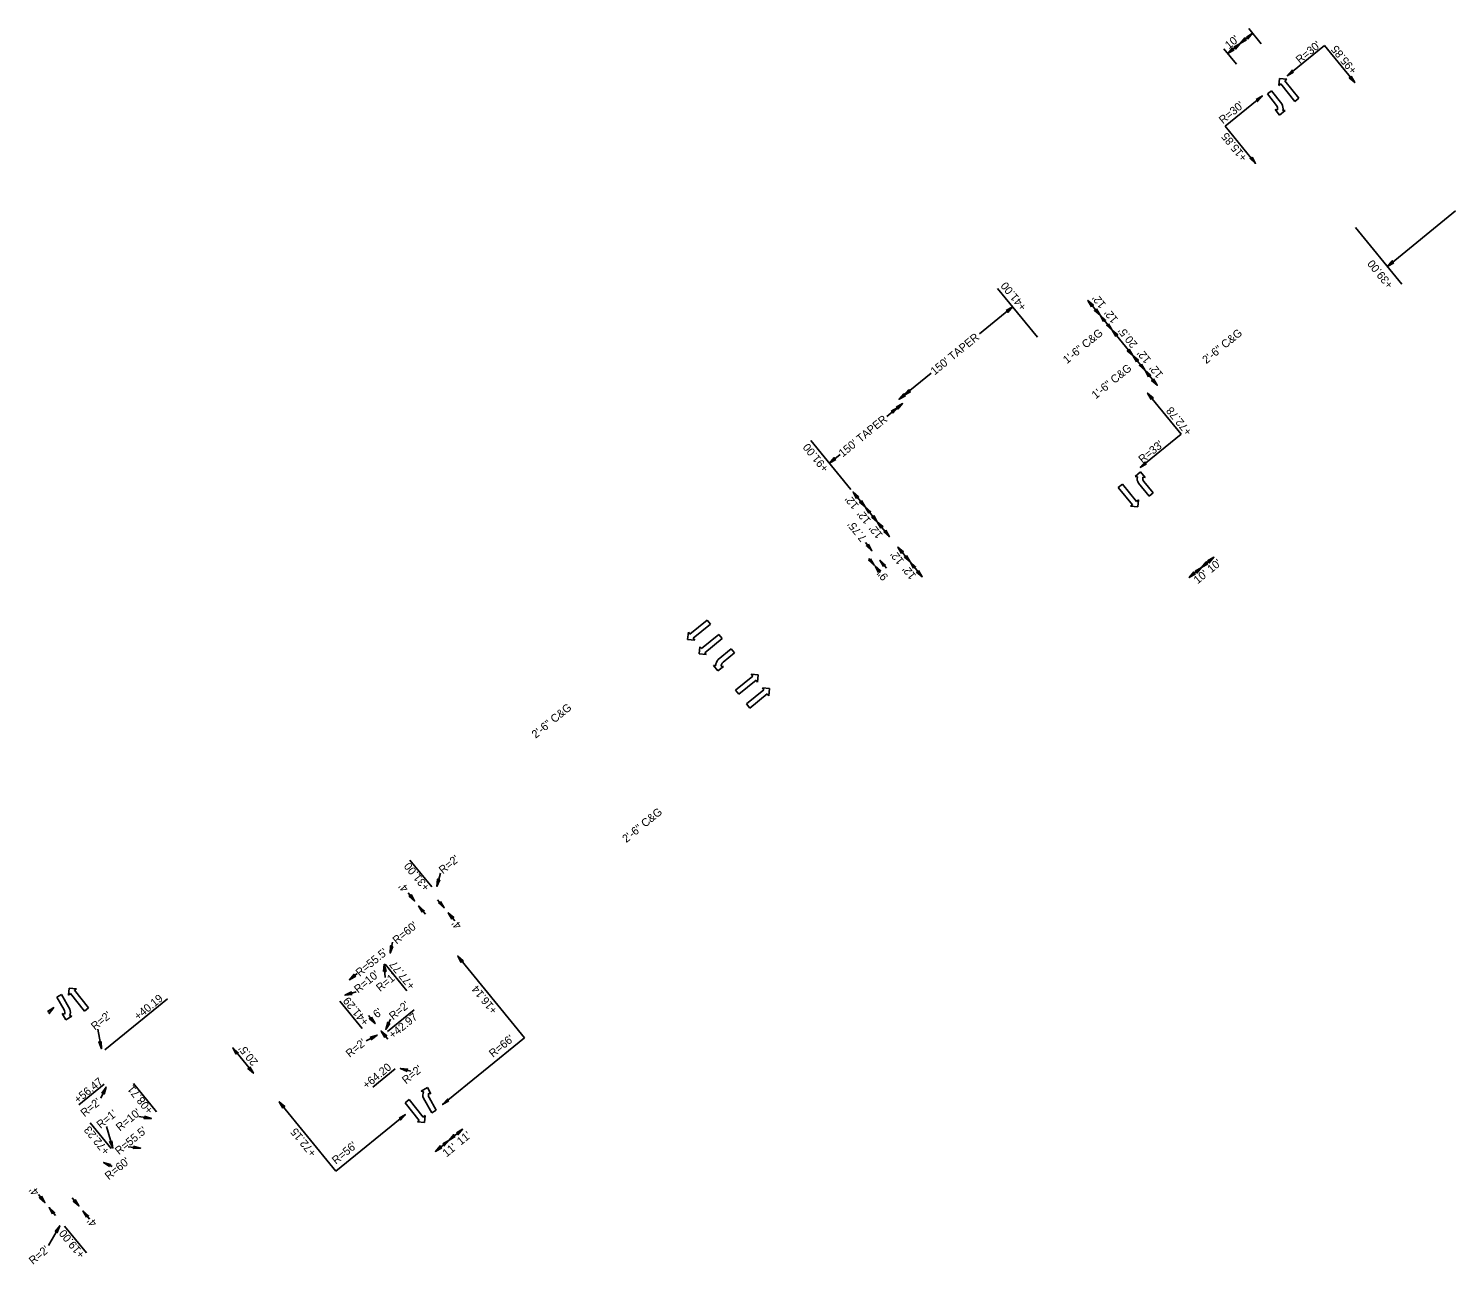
# Model space of a CAD drawing. Extents: x 2320991 to 2332664, y 598057 to 612602.
# Drawn here: x 2322910 to 2323802, y 599000 to 599773 of the extents above; entities that cross this region are included whole.
import ezdxf

# ---------------------------------------------------------------- set-up
doc = ezdxf.new("R2010")
doc.units = 0
for name, color, linetype in [('Prop Dimension', 7, 'Continuous'), ('Prop Dimension Text', 7, 'Continuous'), ('Prop Lane Arrow CELL', 7, 'Continuous'), ('Prop Terminator CELL', 7, 'Continuous')]:
    doc.layers.add(name, color=color, linetype=linetype)

msp = doc.modelspace()

# ---------------------------------------------------------------- linework, layer by layer
at = {"layer": 'Prop Dimension'}
for p, q in [((2323660.06, 599757.48), (2323675.51, 599770.18)), ((2323697.16, 599743.67), (2323720.4, 599762.64)), ((2323739.37, 599739.4), (2323720.4, 599762.64)), ((2323681.66, 599731.02), (2323658.42, 599712.05)), ((2323677.4, 599688.81), (2323658.42, 599712.05)), ((2323759.79, 599624.48), (2323802.28, 599659.17)), ((2323739.91, 599648.83), (2323768.82, 599613.43)), ((2323516.03, 599610.67), (2323540.97, 599580.12)), ((2323504.78, 599582.33), (2323525.41, 599599.18)), ((2323572.54, 599603.2), (2323580.13, 599593.91)), ((2323580.13, 599593.91), (2323587.72, 599584.61)), ((2323587.72, 599584.61), (2323600.68, 599568.73)), ((2323600.68, 599568.73), (2323608.27, 599559.44)), ((2323454.59, 599541.36), (2323474.68, 599557.76)), ((2323608.27, 599559.44), (2323615.86, 599550.14)), ((2323609.89, 599545.27), (2323630.81, 599519.65)), ((2323446.89, 599530.69), (2323456.74, 599538.73)), ((2323605.25, 599498.78), (2323630.81, 599519.65)), ((2323399.49, 599515.53), (2323424.48, 599484.91)), ((2323411.02, 599501.41), (2323417.66, 599506.83)), ((2323433.34, 599474.07), (2323425.75, 599483.36)), ((2323440.93, 599464.77), (2323433.34, 599474.07)), ((2323448.52, 599455.47), (2323440.93, 599464.77)), ((2323433.5, 599451.76), (2323437.62, 599446.73)), ((2323461.41, 599439.68), (2323453.82, 599448.98)), ((2323435.71, 599441.78), (2323439.03, 599437.72)), ((2323439.5, 599437.14), (2323442.81, 599433.09)), ((2323442.52, 599440.72), (2323446.63, 599435.69)), ((2323469, 599430.39), (2323461.41, 599439.68)), ((2323635.86, 599429.91), (2323651.31, 599442.61)), ((2323162.54, 599236.53), (2323148.86, 599253.29)), ((2323165.72, 599236.83), (2323167.87, 599245.04)), ((2323147.65, 599232.76), (2323151.76, 599227.73)), ((2323154.29, 599224.63), (2323158.48, 599219.49)), ((2323166.14, 599228.5), (2323170.25, 599223.46)), ((2323172.78, 599220.36), (2323176.98, 599215.23)), ((2323136.52, 599195.11), (2323138.03, 599202.04)), ((2323132.77, 599188.15), (2323133.42, 599179.98)), ((2323133.32, 599188.15), (2323146.88, 599171.53)), ((2323178.69, 599193.24), (2323220.39, 599142.17)), ((2323115.8, 599182.37), (2323110.97, 599178.43)), ((2323108.17, 599168.73), (2323115.28, 599170.97)), ((2322958.21, 599134.66), (2322997.35, 599166.61)), ((2323105.06, 599165.08), (2323118.96, 599148.05)), ((2323134.9, 599146.21), (2323151.4, 599159.68)), ((2323127.04, 599151.07), (2323122.92, 599156.11)), ((2323133.72, 599147.47), (2323136.78, 599153.88)), ((2322956.01, 599135.29), (2322953.71, 599147.52)), ((2323128.4, 599143.88), (2323121.56, 599140.29)), ((2323130.83, 599146.42), (2323134.94, 599141.38)), ((2323169.26, 599100.43), (2323220.39, 599142.17)), ((2323038.06, 599135.88), (2323051.03, 599120)), ((2323125.61, 599111.23), (2323139.66, 599122.7)), ((2323142.9, 599123.03), (2323149.34, 599121.36)), ((2322957.72, 599113.16), (2322941.96, 599100.3)), ((2322958.89, 599111.4), (2322955.66, 599104.42)), ((2322990.35, 599095.95), (2322976, 599113.53)), ((2323067.16, 599102.18), (2323102.61, 599058.75)), ((2322962.09, 599072.88), (2322948.88, 599089.06)), ((2322987.28, 599091.82), (2322979.47, 599092.96)), ((2323145.99, 599094.17), (2323102.61, 599058.75)), ((2322963.17, 599073.19), (2322959.13, 599086.63)), ((2323164.73, 599071.16), (2323181.79, 599085.05)), ((2322980.47, 599073.27), (2322972.63, 599074.06)), ((2322957.32, 599064.22), (2322962.68, 599061.73)), ((2322916.63, 599044.16), (2322920.74, 599039.13)), ((2322923.27, 599036.03), (2322927.38, 599031)), ((2322937.83, 599042.11), (2322941.94, 599037.07)), ((2322944.47, 599033.97), (2322948.66, 599028.84)), ((2322944.47, 599033.97), (2322948.58, 599028.94)), ((2322929.95, 599024.7), (2322922.92, 599012.38)), ((2322932.87, 599024.5), (2322946.63, 599007.65))]:
    msp.add_line(p, q, dxfattribs=at)
at = {"layer": 'Prop Dimension Text'}
for p, q in [((2323680.87, 599763.61), (2323673.07, 599773.17)), ((2323665.38, 599750.96), (2323657.58, 599760.52))]:
    msp.add_line(p, q, dxfattribs=at)
at = {"layer": 'Prop Lane Arrow CELL'}
for p, q in [((2323691.9, 599737.55), (2323692.32, 599741.95)), ((2323692.32, 599741.95), (2323696.79, 599741.52)), ((2323696.79, 599741.52), (2323695.63, 599740.57)), ((2323695.63, 599740.57), (2323704.45, 599729.7)), ((2323684.73, 599732.28), (2323687.33, 599734.31)), ((2323690.38, 599725.08), (2323684.73, 599732.28)), ((2323687.33, 599734.31), (2323693.84, 599726.01)), ((2323693.07, 599738.49), (2323691.9, 599737.55)), ((2323701.89, 599727.62), (2323693.07, 599738.49)), ((2323692.36, 599719.07), (2323689.54, 599722.58)), ((2323689.54, 599722.58), (2323691.01, 599722.4)), ((2323695.79, 599721.82), (2323692.36, 599719.07)), ((2323694.31, 599722), (2323695.79, 599721.82)), ((2323704.45, 599729.7), (2323701.89, 599727.62)), ((2323602.11, 599493.12), (2323605.5, 599495.93)), ((2323603.59, 599492.96), (2323602.11, 599493.12)), ((2323605.5, 599495.93), (2323608.37, 599492.46)), ((2323608.37, 599492.46), (2323606.89, 599492.61)), ((2323607.57, 599489.95), (2323613.33, 599482.84)), ((2323591.56, 599486.32), (2323594.13, 599488.4)), ((2323600.39, 599475.45), (2323591.56, 599486.32)), ((2323594.13, 599488.4), (2323602.95, 599477.53)), ((2323610.76, 599480.76), (2323604.13, 599488.96)), ((2323613.33, 599482.84), (2323610.76, 599480.76)), ((2323599.22, 599474.5), (2323600.39, 599475.45)), ((2323603.69, 599474.07), (2323599.22, 599474.5)), ((2323602.95, 599477.53), (2323604.11, 599478.47)), ((2323604.11, 599478.47), (2323603.69, 599474.07)), ((2323323.79, 599394.55), (2323334.66, 599403.37)), ((2323336.74, 599400.81), (2323325.87, 599391.99)), ((2323334.66, 599403.37), (2323336.74, 599400.81)), ((2323322.41, 599391.24), (2323322.84, 599395.71)), ((2323326.81, 599390.82), (2323322.41, 599391.24)), ((2323322.84, 599395.71), (2323323.79, 599394.55)), ((2323325.87, 599391.99), (2323326.81, 599390.82)), ((2323330.99, 599385.5), (2323341.86, 599394.32)), ((2323343.94, 599391.76), (2323333.07, 599382.94)), ((2323341.86, 599394.32), (2323343.94, 599391.76)), ((2323329.62, 599382.19), (2323330.05, 599386.66)), ((2323334.02, 599381.77), (2323329.62, 599382.19)), ((2323330.05, 599386.66), (2323330.99, 599385.5)), ((2323333.07, 599382.94), (2323334.02, 599381.77)), ((2323349.58, 599385.34), (2323341.41, 599378.66)), ((2323344.58, 599376.99), (2323351.67, 599382.78)), ((2323351.67, 599382.78), (2323349.58, 599385.34)), ((2323340.06, 599374.86), (2323338.58, 599375)), ((2323338.58, 599375), (2323341.33, 599371.56)), ((2323341.33, 599371.56), (2323344.85, 599374.37)), ((2323344.85, 599374.37), (2323343.37, 599374.52)), ((2323352.22, 599359.48), (2323363.09, 599368.3)), ((2323365.17, 599365.74), (2323354.3, 599356.92)), ((2323363.09, 599368.3), (2323362.15, 599369.47)), ((2323362.15, 599369.47), (2323366.55, 599369.04)), ((2323366.12, 599364.58), (2323365.17, 599365.74)), ((2323366.55, 599369.04), (2323366.12, 599364.58)), ((2323354.3, 599356.92), (2323352.22, 599359.48)), ((2323359.22, 599350.91), (2323370.09, 599359.73)), ((2323372.17, 599357.17), (2323361.3, 599348.35)), ((2323370.09, 599359.73), (2323369.14, 599360.9)), ((2323369.14, 599360.9), (2323373.54, 599360.47)), ((2323373.11, 599356), (2323372.17, 599357.17)), ((2323373.54, 599360.47), (2323373.11, 599356)), ((2323361.3, 599348.35), (2323359.22, 599350.91)), ((2322928.2, 599167.6), (2322931.07, 599169.23)), ((2322931.07, 599169.23), (2322936.27, 599160.05)), ((2322935.5, 599168.85), (2322935.92, 599173.25)), ((2322936.66, 599169.8), (2322935.5, 599168.85)), ((2322935.92, 599173.25), (2322940.39, 599172.82)), ((2322945.48, 599158.93), (2322936.66, 599169.8)), ((2322940.39, 599172.82), (2322939.22, 599171.88)), ((2322939.22, 599171.88), (2322948.04, 599161.01)), ((2322932.71, 599159.64), (2322928.2, 599167.6)), ((2322948.04, 599161.01), (2322945.48, 599158.93)), ((2322933.78, 599153.41), (2322931.52, 599157.3)), ((2322931.52, 599157.3), (2322932.95, 599156.9)), ((2322937.58, 599155.62), (2322933.78, 599153.41)), ((2322936.15, 599156.02), (2322937.58, 599155.62)), ((2323155.93, 599108.82), (2323159.73, 599111.04)), ((2323157.36, 599108.43), (2323155.93, 599108.82)), ((2323159.73, 599111.04), (2323162, 599107.15)), ((2323162, 599107.15), (2323160.57, 599107.54)), ((2323145.8, 599101.43), (2323148.36, 599103.51)), ((2323154.62, 599090.56), (2323145.8, 599101.43)), ((2323148.36, 599103.51), (2323157.18, 599092.64)), ((2323162.45, 599095.22), (2323157.24, 599104.39)), ((2323160.8, 599104.8), (2323165.32, 599096.84)), ((2323165.32, 599096.84), (2323162.45, 599095.22)), ((2323153.46, 599089.62), (2323154.62, 599090.56)), ((2323157.93, 599089.19), (2323153.46, 599089.62)), ((2323157.18, 599092.64), (2323158.35, 599093.59)), ((2323158.35, 599093.59), (2323157.93, 599089.19))]:
    msp.add_line(p, q, dxfattribs=at)
for centre, radius, start, end in [((2323687.82, 599723.06), 3.27, 348.43667, 38.09484), ((2323689.28, 599723.44), 5.25, 344.10707, 29.41877), ((2323608.65, 599491.6), 5.25, 165.00564, 210.31734), ((2323610.1, 599492.01), 3.27, 169.33523, 218.99341), ((2323345.29, 599375.16), 5.25, 137.90406, 183.21576), ((2323346.63, 599374.46), 3.27, 129.22799, 178.88617), ((2322929.88, 599158.02), 3.27, 339.9172, 29.57538), ((2322931.38, 599158.19), 5.25, 335.58761, 20.89931), ((2323162.13, 599106.26), 5.25, 155.58761, 200.89931), ((2323163.63, 599106.42), 3.27, 159.9172, 209.57538)]:
    msp.add_arc(centre, radius, start, end, dxfattribs=at)
at = {"layer": 'Prop Terminator CELL'}
for points in [[(2323671.72, 599766.16), (2323667.79, 599763.83), (2323670.71, 599767.37), (2323670.79, 599766.39)], [(2323671.58, 599767.85), (2323675.51, 599770.18), (2323672.58, 599766.64), (2323672.5, 599767.62)], [(2323663.99, 599759.8), (2323660.06, 599757.48), (2323662.99, 599761.02), (2323663.07, 599760.04)], [(2323663.86, 599761.5), (2323667.79, 599763.83), (2323664.86, 599760.28), (2323664.78, 599761.27)], [(2323701.13, 599745.91), (2323697.16, 599743.67), (2323700.16, 599747.15), (2323700.22, 599746.16)], [(2323737.12, 599743.38), (2323739.37, 599739.4), (2323735.89, 599742.4), (2323736.87, 599742.46)], [(2323677.69, 599728.77), (2323681.66, 599731.02), (2323678.66, 599727.54), (2323678.6, 599728.52)], [(2323675.15, 599692.78), (2323677.4, 599688.81), (2323673.92, 599691.81), (2323674.9, 599691.87)], [(2323763.77, 599626.73), (2323759.79, 599624.48), (2323762.79, 599627.97), (2323762.85, 599626.98)], [(2323521.44, 599596.93), (2323525.41, 599599.18), (2323522.42, 599595.69), (2323522.35, 599596.68)], [(2323574.79, 599599.23), (2323572.54, 599603.2), (2323576.02, 599600.2), (2323575.04, 599600.14)], [(2323577.88, 599597.88), (2323580.13, 599593.91), (2323576.65, 599596.91), (2323577.63, 599596.97)], [(2323582.38, 599589.93), (2323580.13, 599593.91), (2323583.61, 599590.91), (2323582.63, 599590.85)], [(2323585.47, 599588.59), (2323587.72, 599584.61), (2323584.24, 599587.61), (2323585.22, 599587.67)], [(2323589.96, 599580.64), (2323587.72, 599584.61), (2323591.2, 599581.61), (2323590.22, 599581.55)], [(2323598.44, 599572.71), (2323600.68, 599568.73), (2323597.2, 599571.73), (2323598.19, 599571.79)], [(2323602.93, 599564.76), (2323600.68, 599568.73), (2323604.16, 599565.73), (2323603.18, 599565.67)], [(2323606.03, 599563.41), (2323608.27, 599559.44), (2323604.79, 599562.44), (2323605.77, 599562.5)], [(2323610.52, 599555.46), (2323608.27, 599559.44), (2323611.75, 599556.44), (2323610.77, 599556.38)], [(2323613.62, 599554.12), (2323615.86, 599550.14), (2323612.38, 599553.14), (2323613.36, 599553.2)], [(2323458.57, 599543.6), (2323454.59, 599541.36), (2323457.59, 599544.84), (2323457.65, 599543.86)], [(2323461.63, 599546.1), (2323457.65, 599543.86), (2323460.65, 599547.34), (2323460.71, 599546.35)], [(2323612.14, 599541.29), (2323609.89, 599545.27), (2323613.37, 599542.27), (2323612.39, 599542.21)], [(2323449.7, 599533.99), (2323453.68, 599536.23), (2323450.68, 599532.75), (2323450.62, 599533.74)], [(2323452.76, 599536.49), (2323456.74, 599538.73), (2323453.74, 599535.25), (2323453.68, 599536.23)], [(2323415, 599503.65), (2323411.02, 599501.41), (2323414.02, 599504.89), (2323414.08, 599503.9)], [(2323609.22, 599501.02), (2323605.25, 599498.78), (2323608.25, 599502.26), (2323608.31, 599501.28)], [(2323428, 599479.39), (2323425.75, 599483.36), (2323429.23, 599480.37), (2323428.25, 599480.31)], [(2323431.09, 599478.05), (2323433.34, 599474.07), (2323429.86, 599477.07), (2323430.84, 599477.13)], [(2323435.59, 599470.09), (2323433.34, 599474.07), (2323436.82, 599471.07), (2323435.84, 599471.01)], [(2323438.68, 599468.75), (2323440.93, 599464.77), (2323437.45, 599467.77), (2323438.43, 599467.83)], [(2323443.18, 599460.79), (2323440.93, 599464.77), (2323444.41, 599461.77), (2323443.43, 599461.71)], [(2323446.28, 599459.45), (2323448.52, 599455.47), (2323445.04, 599458.47), (2323446.02, 599458.53)], [(2323435.37, 599450.7), (2323437.62, 599446.73), (2323434.13, 599449.73), (2323435.12, 599449.79)], [(2323456.07, 599445), (2323453.82, 599448.98), (2323457.31, 599445.98), (2323456.32, 599445.92)], [(2323436.78, 599441.7), (2323439.03, 599437.72), (2323435.54, 599440.72), (2323436.53, 599440.78)], [(2323441.75, 599433.17), (2323439.5, 599437.14), (2323442.98, 599434.14), (2323442, 599434.08)], [(2323444.76, 599436.75), (2323442.52, 599440.72), (2323446, 599437.72), (2323445.01, 599437.66)], [(2323459.17, 599443.66), (2323461.41, 599439.68), (2323457.93, 599442.68), (2323458.91, 599442.74)], [(2323463.66, 599435.71), (2323461.41, 599439.68), (2323464.89, 599436.68), (2323463.91, 599436.62)], [(2323639.66, 599433.93), (2323643.59, 599436.26), (2323640.66, 599432.72), (2323640.58, 599433.7)], [(2323647.52, 599438.59), (2323643.59, 599436.26), (2323646.51, 599439.8), (2323646.59, 599438.82)], [(2323647.38, 599440.29), (2323651.31, 599442.61), (2323648.38, 599439.07), (2323648.3, 599440.05)], [(2323466.76, 599434.36), (2323469, 599430.39), (2323465.52, 599433.39), (2323466.5, 599433.45)], [(2323639.79, 599432.24), (2323635.86, 599429.91), (2323638.79, 599433.45), (2323638.87, 599432.47)], [(2323167.61, 599240.98), (2323165.72, 599236.83), (2323166.09, 599241.41), (2323166.72, 599240.65)], [(2323149.51, 599231.7), (2323151.76, 599227.73), (2323148.28, 599230.73), (2323149.26, 599230.79)], [(2323156.53, 599220.65), (2323154.29, 599224.63), (2323157.77, 599221.63), (2323156.79, 599221.57)], [(2323168.01, 599227.44), (2323170.25, 599223.46), (2323166.77, 599226.46), (2323167.76, 599226.52)], [(2323175.03, 599216.39), (2323172.78, 599220.36), (2323176.26, 599217.37), (2323175.28, 599217.31)], [(2323138.23, 599199.34), (2323136.52, 599195.11), (2323136.7, 599199.7), (2323137.36, 599198.97)], [(2323132.36, 599183.6), (2323132.77, 599188.15), (2323133.93, 599183.7), (2323133.08, 599184.21)], [(2323180.94, 599189.26), (2323178.69, 599193.24), (2323182.18, 599190.24), (2323181.19, 599190.18)], [(2323114.95, 599180.67), (2323110.97, 599178.43), (2323113.97, 599181.91), (2323114.03, 599180.93)], [(2323112.7, 599169.35), (2323108.17, 599168.73), (2323112.25, 599170.86), (2323111.94, 599169.92)], [(2322922.38, 599158.52), (2322926.19, 599161.03), (2322923.44, 599157.36), (2322923.31, 599158.33)], [(2323124.79, 599155.04), (2323127.04, 599151.07), (2323123.56, 599154.07), (2323124.54, 599154.13)], [(2323136.36, 599151.2), (2323133.72, 599147.47), (2323134.95, 599151.9), (2323135.42, 599151.04)], [(2323124.06, 599142.47), (2323128.4, 599143.88), (2323124.77, 599141.07), (2323124.91, 599142.04)], [(2323133.08, 599142.44), (2323130.83, 599146.42), (2323134.31, 599143.42), (2323133.33, 599143.36)], [(2322955.94, 599139.86), (2322956.01, 599135.29), (2322954.38, 599139.59), (2322955.28, 599139.17)], [(2323040.31, 599131.9), (2323038.06, 599135.88), (2323041.55, 599132.88), (2323040.56, 599132.82)], [(2323048.78, 599123.97), (2323051.03, 599120), (2323047.55, 599123), (2323048.53, 599123.06)], [(2323147.06, 599121.15), (2323142.9, 599123.03), (2323147.48, 599122.67), (2323146.72, 599122.04)], [(2322956.29, 599107.64), (2322958.89, 599111.4), (2322957.71, 599106.96), (2322957.23, 599107.82)], [(2323069.4, 599098.2), (2323067.16, 599102.18), (2323070.64, 599099.18), (2323069.65, 599099.12)], [(2323173.24, 599102.68), (2323169.26, 599100.43), (2323172.26, 599103.91), (2323172.32, 599102.93)], [(2322982.93, 599093.24), (2322987.28, 599091.82), (2322982.68, 599091.68), (2322983.37, 599092.39)], [(2323142.01, 599091.92), (2323145.99, 599094.17), (2323142.99, 599090.69), (2323142.93, 599091.67)], [(2323177.2, 599080.42), (2323173.26, 599078.11), (2323176.2, 599081.64), (2323176.28, 599080.65)], [(2323177.85, 599082.75), (2323181.79, 599085.05), (2323178.85, 599081.53), (2323178.77, 599082.51)], [(2322962.61, 599077.72), (2322963.17, 599073.19), (2322961.1, 599077.29), (2322962.03, 599076.97)], [(2322976.07, 599074.49), (2322980.47, 599073.27), (2322975.89, 599072.93), (2322976.54, 599073.67)], [(2323168.67, 599073.46), (2323164.73, 599071.16), (2323167.67, 599074.68), (2323167.75, 599073.7)], [(2323169.32, 599075.8), (2323173.26, 599078.11), (2323170.32, 599074.58), (2323170.24, 599075.56)], [(2322961.07, 599061.62), (2322957.32, 599064.22), (2322961.76, 599063.04), (2322960.9, 599062.56)], [(2322918.5, 599043.11), (2322920.74, 599039.13), (2322917.26, 599042.13), (2322918.25, 599042.19)], [(2322925.52, 599032.06), (2322923.27, 599036.03), (2322926.75, 599033.03), (2322925.77, 599032.97)], [(2322939.7, 599041.05), (2322941.94, 599037.07), (2322938.46, 599040.07), (2322939.44, 599040.13)], [(2322946.72, 599030), (2322944.47, 599033.97), (2322947.95, 599030.97), (2322946.97, 599030.91)], [(2322927.04, 599021.17), (2322929.95, 599024.7), (2322928.4, 599020.37), (2322927.99, 599021.27)]]:
    msp.add_lwpolyline(points, close=True, dxfattribs=at)

# ---------------------------------------------------------------- texts
at = {"layer": 'Prop Dimension'}
for s, rotation, p in [('+95.85', 129.22799, (2323741.05, 599747.18)), ('+15.85', 129.22799, (2323672.46, 599692.64)), ('+39.00', 129.22799, (2323763.71, 599613.1)), ('+41.00', 129.22799, (2323534.54, 599599.29)), ('+72.78', 129.22799, (2323637.93, 599521.21)), ('+91.00', 129.22799, (2323410.89, 599498.35)), ('+31.00', 129.22799, (2323161.6, 599236.42)), ('+77.77', 129.22799, (2323152.49, 599174.86)), ('+40.19', 39.22799, (2322978.97, 599152.93)), ('+16.14', 129.22799, (2323203.91, 599159.48)), ('+41.29', 129.22799, (2323123.52, 599152.24)), ('+42.97', 39.22799, (2323138.07, 599141.27)), ('+64.20', 39.22799, (2323121.73, 599109.9)), ('+56.47', 39.22799, (2322941.38, 599100.83)), ('+08.71', 129.22799, (2322988.71, 599097.05)), ('+72.23', 129.22799, (2322961.57, 599071.52)), ('+72.15', 129.22799, (2323090.68, 599070.3)), ('+19.00', 129.22799, (2322946, 599006.83))]:
    msp.add_text(s, height=5, rotation=rotation, dxfattribs=at).set_placement(p)
at = {"layer": 'Prop Dimension Text'}
for s, rotation, p in [("10'", 39.43857, (2323660.72, 599760.04)), ("R=30'", 39.22799, (2323705.01, 599750.91)), ("R=30'", 39.22799, (2323656.97, 599713.23)), ("12'", 129.22799, (2323584.15, 599600.72)), ("12'", 129.22799, (2323591.73, 599591.42)), ("150' TAPER", 39.22799, (2323476.75, 599556.22)), ('1\'-6" C&G', 39.22799, (2323559.47, 599563.31)), ("20.5'", 129.22799, (2323603.86, 599575.9)), ('2\'-6" C&G', 39.22799, (2323646.56, 599563.26)), ("12'", 129.22799, (2323612.29, 599566.24)), ('1\'-6" C&G', 39.22799, (2323577.45, 599541.28)), ("12'", 129.22799, (2323619.88, 599556.95)), ("150' TAPER", 39.22799, (2323419.3, 599504.94)), ("R=33'", 39.22799, (2323606.64, 599501.14)), ("12'", 129.22799, (2323429.66, 599475.06)), ("7.75'", 129.22799, (2323434.7, 599454.79)), ("12'", 129.22799, (2323437.25, 599465.77)), ("12'", 129.22799, (2323444.66, 599456.69)), ("12'", 129.22799, (2323457.94, 599440.43)), ("12'", 129.22799, (2323465.53, 599431.14)), ("10'", 39.43857, (2323649.69, 599432.57)), ('9"', 129.22799, (2323448.07, 599430.54)), ("10'", 39.43857, (2323641.18, 599425.67)), ('2\'-6" C&G', 39.22799, (2323227.41, 599329.09)), ('2\'-6" C&G', 39.22799, (2323284.05, 599263.84)), ("R=2'", 39.22799, (2323169.42, 599244.33)), ("4'", 129.22799, (2323148.32, 599235.71)), ("R=60'", 39.22799, (2323140.51, 599200.41)), ("4'", 129.22799, (2323181.52, 599212.52)), ("R=55.5'", 39.22799, (2323117.44, 599180.18)), ("R=10'", 39.22799, (2323116.43, 599169.81)), ("R=1'", 39.22799, (2323130.22, 599170.74)), ("6'", 39.22799, (2323128.24, 599154.19)), ("R=2'", 39.22799, (2323138.32, 599153.03)), ("R=2'", 39.22799, (2322952.02, 599146.65)), ("R=2'", 39.22799, (2323111.25, 599129.58)), ("R=66'", 39.22799, (2323200.74, 599129.63)), ("20.5'", 129.22799, (2323054.2, 599127.17)), ("R=2'", 39.22799, (2323146.39, 599112.98)), ("R=2'", 39.22799, (2322945.49, 599092.44)), ("R=1'", 39.22799, (2322955.52, 599085.13)), ("R=10'", 39.22799, (2322967.58, 599083.52)), ("R=55.5'", 39.22799, (2322967.03, 599068.74)), ("11'", 39.167, (2323180.69, 599074.77)), ("R=56'", 39.22799, (2323102.6, 599062.79)), ("11'", 39.167, (2323171.72, 599067.34)), ("R=60'", 39.22799, (2322960.63, 599053.05)), ("4'", 129.22799, (2322917.42, 599045.89)), ("4'", 129.22799, (2322953.6, 599026.45)), ("R=2'", 39.22799, (2322913.2, 599000.12))]:
    msp.add_text(s, height=5, rotation=rotation, dxfattribs=at).set_placement(p)

doc.saveas('drawing.dxf')
